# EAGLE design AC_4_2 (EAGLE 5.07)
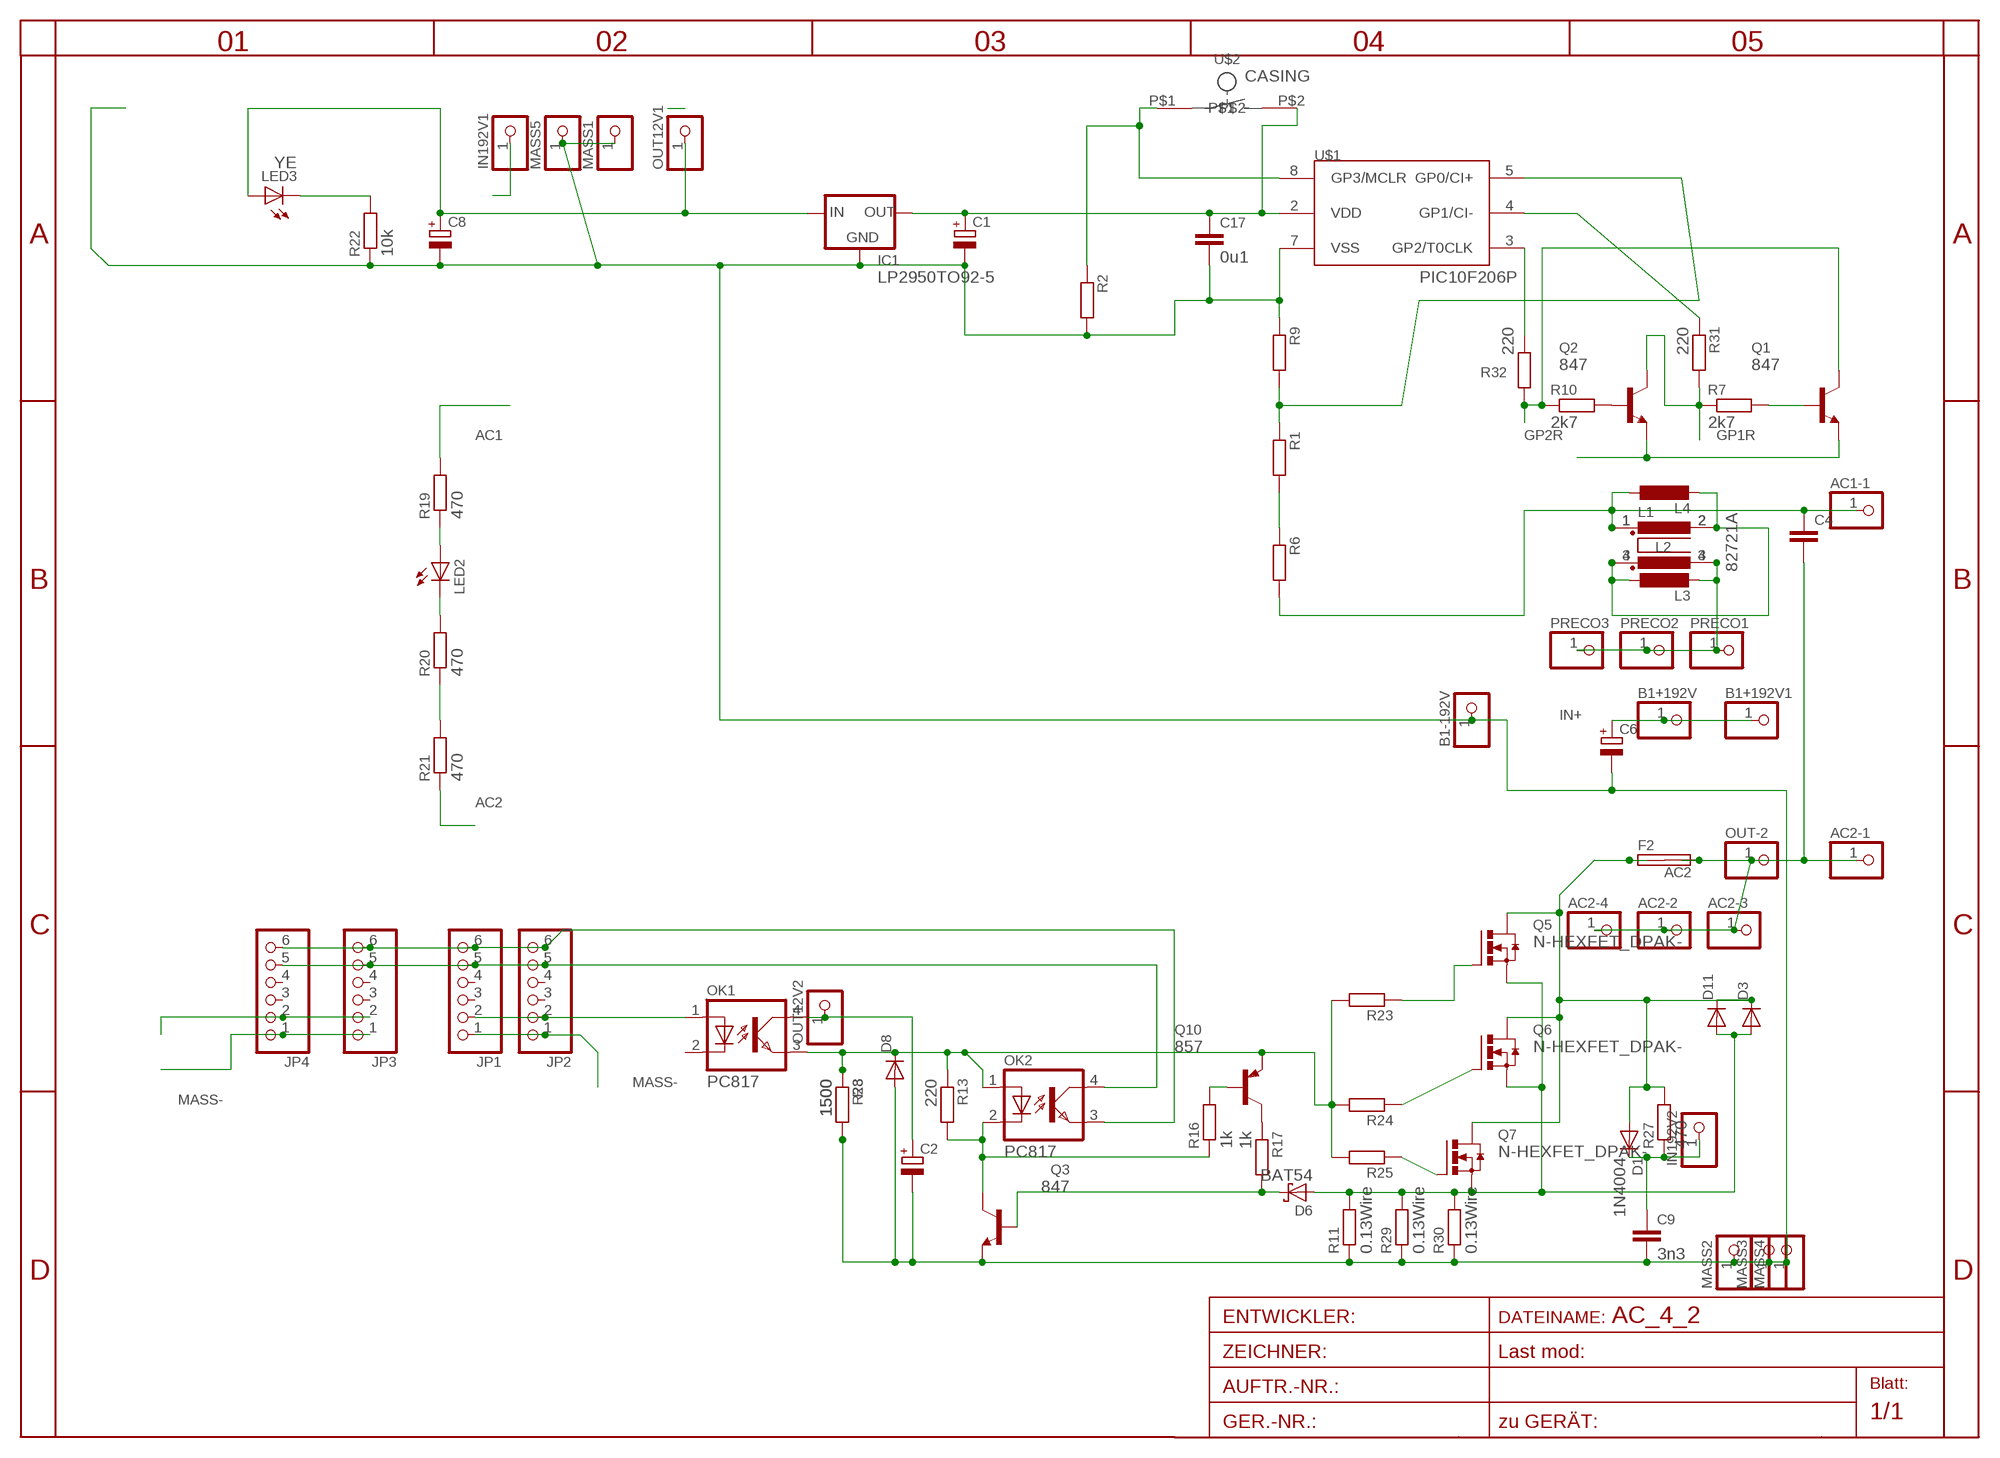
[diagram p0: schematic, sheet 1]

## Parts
AC1-1  PINHD-1X14.5MM  [1X4MM5]
AC2-1  PINHD-1X14.5MM  [1X4MM5]
AC2-2  PINHD-1X12MM3  [1X2MM3]
AC2-3  PINHD-1X12MM3  [1X2MM3]
AC2-4  PINHD-1X12MM3  [1X2MM3]
B1+192V  PINHD-1X12MM3  [1X2MM3]
B1+192V1  PINHD-1X12MM3  [1X2MM3]
B1-192V  PINHD-1X12MM3  [1X2MM3]
C1  CPOL-EUE5-6  [E5-6]
C2  CPOL-EUE2.5-5  [E2,5-5]
C4  C-EU225-108X268  [C225-108X268]
C6  CPOL-EUE10-20  [EB20D]
C8  CPOL-EUE5-5  [E5-5]
C9  3n3  C-EU102-043X133  [C102-043X133]
C17  0u1  C-EUC1206  [C1206]
D1  1N4004  [DO41-10]
D3  DIODE-SMC  [SMC]
D6  BAT54  [SOT23]
D8  DIODE-MINIMELF  [MINIMELF]
D11  DIODE-SMC  [SMC]
F2  SHK20L7MM5  [7MM5]
IC1  LP2950TO92-5  [T092-5]
IN192V1  PINHD-1X11MM6  [1X1MM8]
IN192V2  PINHD-1X11MM0  [1X1MM0]
JP1  PINHD-1X6  [1X06BOX]
JP2  PINHD-1X6  [1X06BOX]
JP3  PINHD-1X6  [1X06BOX]
JP4  PINHD-1X6  [1X06BOX]
L1  R1405VB1  [B1]
L2  82721A  [82721A]
L3  L-EU2200-15.24  [2200-15.24]
L4  L-EU2200-15.24  [2200-15.24]
LED2  LED3MM  [LED3MM]
LED3  YE  LEDCHIPLED_1206  [CHIPLED_1206]
MASS1  PINHD-1X11MM6  [1X1MM8]
MASS2  PINHD-1X11MM0  [1X1MM0]
MASS3  PINHD-1X11MM6  [1X1MM8]
MASS4  PINHD-1X11MM6  [1X1MM8]
MASS5  PINHD-1X11MM6  [1X1MM8]
OK1  PC817  [DIL04]
OK2  PC817  [DIL04]
OUT12V1  PINHD-1X11MM6  [1X1MM8]
OUT12V2  PINHD-1X11MM0  [1X1MM0]
OUT-2  PINHD-1X12MM3  [1X2MM3]
PRECO1  PINHD-1X12MM3  [1X2MM3]
PRECO2  PINHD-1X12MM3  [1X2MM3]
PRECO3  PINHD-1X12MM3  [1X2MM3]
Q1  847  BC847ALT1SMD  [SOT23]
Q2  847  BC847ALT1SMD  [SOT23]
Q3  847  BC846ALT1SMD  [SOT23]
Q5  N-HEXFET_DPAK-  [TO252]
Q6  N-HEXFET_DPAK-  [TO252]
Q7  N-HEXFET_DPAK-  [TO252]
Q10  857  BC857ALT1SMD  [SOT23-BEC]
R1  R-EU_0207/60  [0207/60]
R2  R-EU_R0805  [R0805]
R3  1500  R-EU_R0805  [R0805]
R6  R-EU_0207/10  [0207/10]
R7  2k7  R-EU_R1206  [R1206]
R9  R-EU_R0805  [R0805]
R10  2k7  R-EU_R1206  [R1206]
R11  0.13Wire  R-EU_0204/5  [0204/5]
R13  220  R-EU_R1206  [R1206]
R16  1k  R-EU_R0805  [R0805]
R17  1k  R-EU_R0805  [R0805]
R19  470  R-EU_0204/5  [0204/5]
R20  470  R-EU_0204/2V  [0204V]
R21  470  R-EU_0204/5  [0204/5]
R22  10k  R-EU_R1206  [R1206]
R23  R-EU_0207/15  [0207/15]
R24  R-EU_0207/10  [0207/10]
R25  R-EU_0207/12  [0207/12]
R27  470  R-EU_0207/10  [0207/10]
R28  1500  R-EU_R1206  [R1206]
R29  0.13Wire  R-EU_0204/5  [0204/5]
R30  0.13Wire  R-EU_0204/5  [0204/5]
R31  220  R-EU_R1206  [R1206]
R32  220  R-EU_R1206  [R1206]
U$1  PIC10F206P  [DIL8]
U$2  CASING  [CASING]

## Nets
AC1: AC1-1.1 C4.1 L1.1 L2.1 L4.1 R6.2 R19.2
AC2: AC2-1.1 AC2-2.1 AC2-3.1 AC2-4.1 C4.2 F2.2A F2.2B OUT-2.1 R21.1
BATT+: C8.+ IC1.3(IN) LED3.A OUT12V1.1
D1: D1.A D3.C D11.C F2.1A F2.1B Q5.3(D) Q6.3(D) Q7.3(D) R27.2
GP1R: JP3.2 JP4.2 Q2.3(C) R7.1 R31.2
GP2R: JP1.2 JP2.2 OK1.1(A) Q1.3(C) R10.1 R32.2
GP3: JP1.6 JP2.6 JP3.6 JP4.6 OK2.3(EMIT) R2.1 U$1.8(GP3/MCLR) U$2.P$1
IN+: B1+192V1.1 B1+192V.1 C6.+ IN192V1.1
INN: L1.2 L1.3 L2.2 L2.4 L3.1 L4.2
MASS-: B1-192V.1 C1.- C2.- C6.- C8.- C9.2 C17.2 D8.A IC1.2(GND) JP1.1 JP2.1 JP3.1 JP4.1 MASS1.1 MASS2.1 MASS3.1 MASS4.1 MASS5.1 Q1.2(E) Q2.2(E) Q3.2(E) R2.2 R3.2 R9.1 R11.1 R22.1 R28.2 R29.1 R30.1 U$1.7(VSS)
N$1: R1.1 R9.2 U$1.5(GP0/CI+)
N$2: C2.+ OK1.4(COL) OUT12V2.1
N$3: R1.2 R6.1
N$4: Q2.1(B) R10.2
N$6: LED2.A R19.1
N$7: Q1.1(B) R7.2
N$9: LED2.K(C) R20.2
N$11: D6.3(C) Q3.1(B) R17.2
N$12: OK2.2(C) Q3.3(C) R13.2 R16.1
N$13: R20.1 R21.2
N$15: LED3.C R22.2
N$16: Q10.B R16.2
N$17: Q10.C R17.1
N$20: C9.1 D1.C IN192V2.1 R27.1
N$25: Q7.1(G) R25.1
N$26: Q6.1(G) R24.1
N$27: Q5.1(G) R23.1
N$39: R31.1 U$1.4(GP1/CI-)
N$43: R32.1 U$1.3(GP2/T0CLK)
PP1: D8.C OK1.3(EMIT) OK2.1(A) Q10.E R3.1 R13.1 R23.2 R24.2 R25.2 R28.1
PRECOIL: L1.4 L2.3 L3.2 PRECO1.1 PRECO2.1 PRECO3.1
SRC1: D3.A D6.1(A) D11.A Q5.2(S) Q6.2(S) Q7.2(S) R11.2 R29.2 R30.2
VDD: C1.+ C17.1 IC1.1(OUT) JP1.5 JP2.5 JP3.5 JP4.5 OK2.4(COL) U$1.2(VDD) U$2.P$2
Unconnected: JP1.3 JP1.4 JP2.3 JP2.4 JP3.3 JP3.4 JP4.3 JP4.4 OK1.2(C)

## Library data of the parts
AC1-1 AC2-1-AC2-4 B1+192V B1+192V1 B1-192V IN192V1 IN192V2 MASS1-MASS5 OUT12V1 OUT12V2 OUT-2 PRECO1-PRECO3 = pinhead:PINHD-1X1: PIN HEADER
C1 C2 C8 = rcl-2:CPOL-EU: POLARIZED CAPACITOR, European symbol
C4 = rcl:C-EU: CAPACITOR, European symbol
C6 = rcl:CPOL-EU: POLARIZED CAPACITOR, European symbol
C9 C17 = rcl-2:C-EU: CAPACITOR, European symbol
D1 = diode:1N4004: DIODE
D3 D8 D11 = diode:DIODE-: DIODE
D6 = diode:BAT54: Schottky Diodes
F2 = fuse:SHK20L: FUSE HOLDER 5 x 20 mm, SH contact, SHH1 Schukat, E1073 Buerklin
IC1 = v-reg:LP2950?*: Source: http://cache.national.com/ds/LP/LP2950.pdf
JP1-JP4 = pinhead:PINHD-1X6: PIN HEADER
L1 = inductor-nkl:R1405V: Übertrager (verlustarm) bis typ. 400kHz Power transformer (low loss) up to typ. 400kHz
L2 = inductors:82721A: FILTER
L3 L4 = rcl:L-EU: INDUCTOR, European symbol
LED2 LED3 = led:LED: LED
OK1 OK2 = optocoupler:PC817: SHARP OPTO COUPLER
Q1 Q2 = transistor-npn:BC847*: NPN Transistor
Q3 = transistor-npn:BC846*: NPN Transistor
Q5-Q7 = transistor-power:N-HEXFET_?-*: HEXFET® Power MOSFET
Q10 = transistor-pnp:BC857*: PNP Transistror
R1-R3 R6 R7 R9-R11 R13 R16 R17 R19-R25 R27-R32 = rcl-2:R-EU_: RESISTOR, European symbol
U$1 = microchip-5:PIC10F2*: uPC nW 0,25/0,5k Program Flash memory Comparator
U$2 = button:CASING

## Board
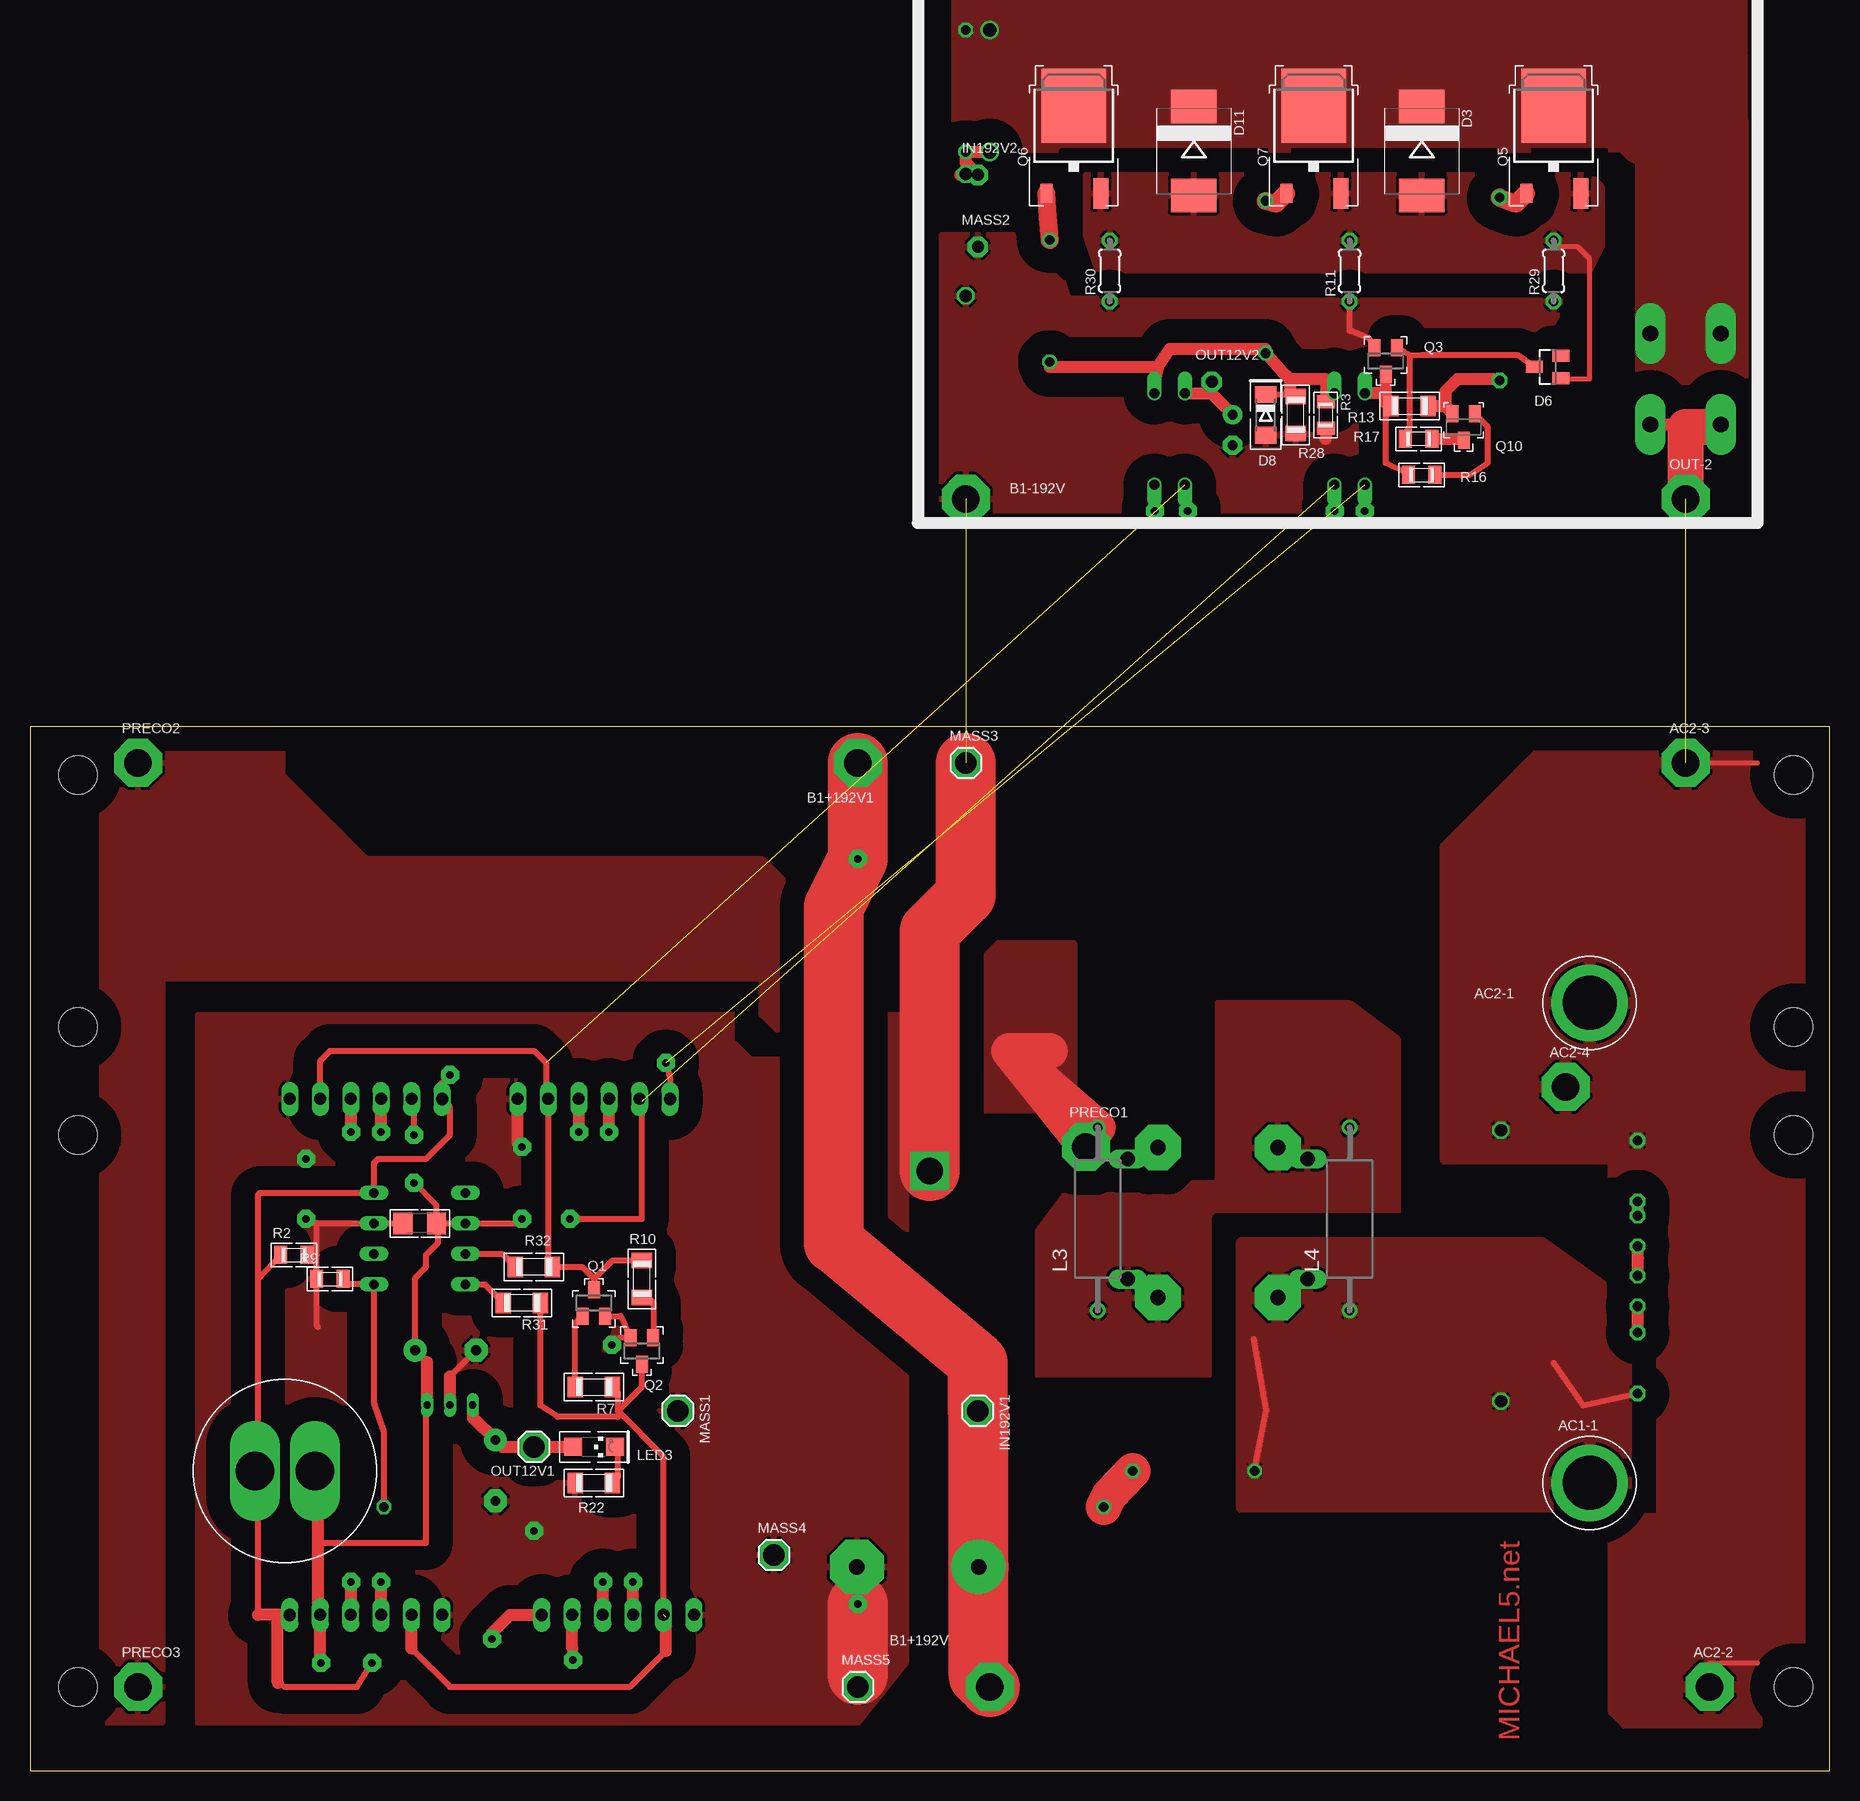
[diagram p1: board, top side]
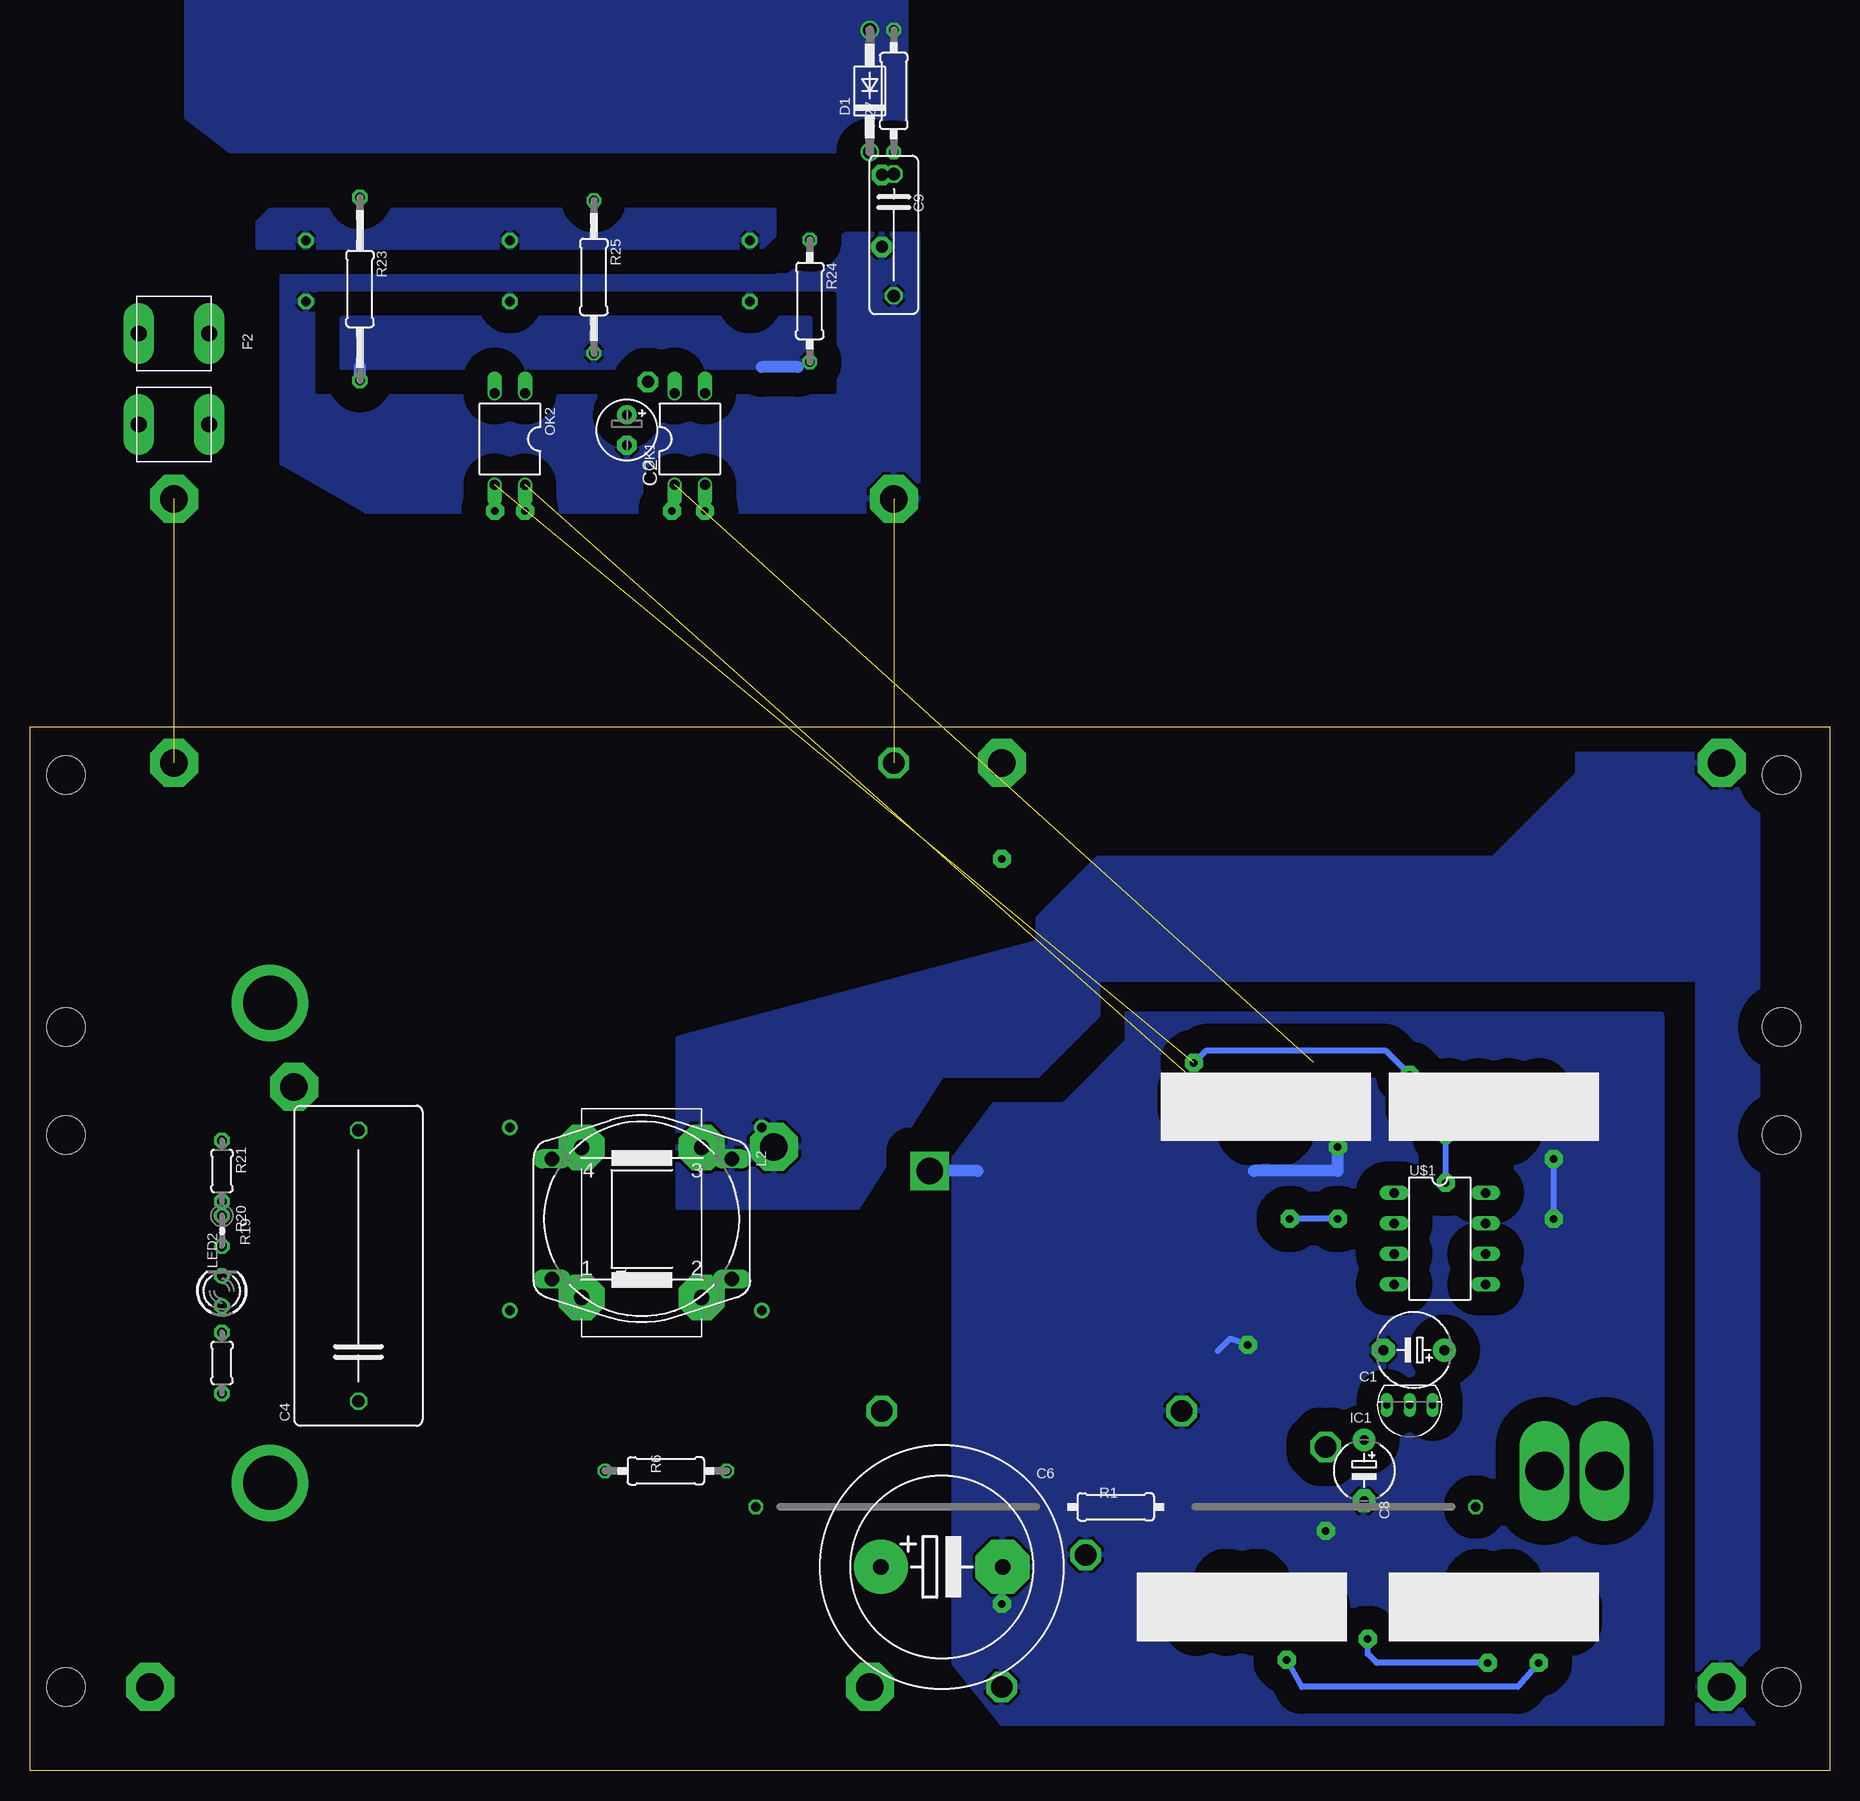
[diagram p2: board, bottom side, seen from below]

Size 150 x 87 mm. Coordinates in mm from the lower left corner, seen from the top.
Outline: 0,0 150,0 150,87 0,87 0,0
Copper layers (1*16): Top 0.035mm / dielectric 1.5mm / Bottom 0.035mm
Design rules "default *": minimum track width 12mil, minimum drill 24mil, track to track 8mil, track to pad 8mil, pad to pad 8mil, via to via 8mil, smd to smd 8mil, copper to edge 40mil, drill to drill 8mil, minimum pad ring 8mil, minimum via ring 8mil, stop-mask expansion 4mil, vias tented up to drill 0mil, thermal gap 10mil
Holes 3.2 mm at 4,83 4,7 4,62 4,53 147,83 147,7 147,62 147,53

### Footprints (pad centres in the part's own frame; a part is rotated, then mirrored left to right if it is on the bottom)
1X4MM5 = drill 4.5 pad 6.35 round: 1 0,0
1X2MM3 = drill 2.3 pad 4 octagon: 1 0,0
E5-6 = drill 0.813 pad 1.905 round: + -2.54,0 | drill 0.813 pad 1.905 octagon: - 2.54,0
E2,5-5 = drill 0.813 pad 1.6 round: + -1.27,0 | drill 0.813 pad 1.6 octagon: - 1.27,0
C225-108X268 = drill 1.016 octagon: 1 -11.303,0; 2 11.303,0
EB20D = drill 1.3 pad 4.5 round: + -5.08,0 | drill 1.3 pad 4.5 octagon: - 5.08,0
E5-5 = drill 0.813 pad 1.905 round: + -2.54,0 | drill 0.813 pad 1.905 octagon: - 2.54,0
C102-043X133 = drill 1.016 octagon: 1 -5.08,0; 2 5.08,0
C1206 = smd 1.6 x 1.8: 1 -1.4,0; 2 1.4,0
DO41-10 = drill 1.118 round: A 5.08,0; C -5.08,0
SMC = smd 2.8 x 3.8: A 3.7,0; C -3.7,0
SOT23 = smd 1 x 1.4: 1 -0.95,-1.1; 2 0.95,-1.1; 3 0,1.1
MINIMELF = smd 1.4 x 1.8: A 1.7,0; C -1.7,0
7MM5 = drill 1.3 pad 2.54 long: 1A -3.8,2.94; 1B -3.8,-2.94; 2A 3.8,2.94; 2B 3.8,-2.94
T092-5 = drill 0.6 pad 0.813 long: 1 -1.905,0; 2 0,0; 3 1.905,0
1X1MM8 = drill 1.8 pad 2.54 octagon: 1 0,0
1X1MM0 = drill 1 pad 1.676 octagon: 1 0,0
1X06BOX = drill 1 long: 1 -6.35,0; 2 -3.81,0; 3 -1.27,0; 4 1.27,0; 5 3.81,0 | drill 1.016 long: 6 6.35,0
B1 = drill 1.27 pad 3.81 octagon: 1 -6.25,5; 2 -6.25,-5; 3 6.25,5; 4 6.25,-5
82721A = drill 1.194 long: 1 7.493,5.004; 2 -7.493,5.004; 3 -7.493,-5.004; 4 7.493,-5.004
2200-15.24 = drill 0.8 pad 1.27 round: 1 -7.62,0; 2 7.62,0
LED3MM = drill 0.8 pad 1.27 octagon: A -1.27,0; K 1.27,0
CHIPLED_1206 = smd 1.5 x 1.5: A 0,-1.75; C 0,1.75
DIL04 = drill 0.813 offset: 1 -1.27,-3.81; 2 1.27,-3.81; 3 1.27,3.81; 4 -1.27,3.81
TO252 = smd 1 x 1.6: 1 -2.28,-3.53 | smd 1.27 x 2.54: 2 2.28,-3.53 | smd 5.4 x 6.2: 3 0,3.77
SOT23-BEC = smd 1 x 1.4: B -0.95,-1.1; C 0,1.1; E 0.95,-1.1
0207/60 = drill 0.813 octagon: 1 -30,0; 2 30,0
R0805 = smd 1.1 x 1.5: 1 -1.1,0; 2 1.1,0
0207/10 = drill 0.813 octagon: 1 -5.08,0; 2 5.08,0
R1206 = smd 1.3 x 1.7: 1 -1.55,0; 2 1.55,0
0204/5 = drill 0.8 pad 1.27 octagon: 1 -2.54,0; 2 2.54,0
0204V = drill 0.8 pad 1.27 octagon: 1 -1.27,0; 2 1.27,0
0207/15 = drill 0.8 pad 1.27 octagon: 1 -7.62,0; 2 7.62,0
0207/12 = drill 0.813 octagon: 1 -6.35,0; 2 6.35,0
DIL8 = drill 0.8 long: 1 -3.81,-3.81; 2 -1.27,-3.81; 3 1.27,-3.81; 4 3.81,-3.81; 5 3.81,3.81; 6 1.27,3.81; 7 -1.27,3.81; 8 -3.81,3.81
CASING = drill 3.2 pad 3.81 long: P$1 -2.5,0; P$2 2.5,0

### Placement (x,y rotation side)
AC1-1  130,24 0 top
AC2-1  130,64 0 top
AC2-2  140,7 0 top
AC2-3  138,84 0 top
AC2-4  128,57 0 top
B1+192V  80,7 0 top
B1+192V1  69,84 180 top
B1-192V  not placed on the board
C1  34.65,35.07 180 bottom
C2  100.25,111.75 270 bottom  (outside the outline)
C4  122.62,42.1 90 bottom
C6  74,17 0 bottom
C8  38.8,25.05 270 bottom
C9  78,128 270 bottom  (outside the outline)
C17  32.49,45.63 180 top
D1  80,140 90 bottom  (outside the outline)
D3  not placed on the board
D6  126.5,117 90 top  (outside the outline)
D8  103,113 270 top  (outside the outline)
D11  not placed on the board
F2  138,116 270 bottom  (outside the outline)
IC1  35,30.5 180 bottom
IN192V1  79,30 270 top
IN192V2  79,133 0 top  (outside the outline)
JP1  47,56 180 bottom
JP2  28,56 180 bottom
JP3  28,13 0 bottom
JP4  49,13 0 bottom
L1  99.03,45.7 90 bottom
L2  99,46 180 bottom
L3  89,46 90 top
L4  110,46 90 top
LED2  134,40 90 bottom
LED3  47,27 270 top
MASS1  54,30 270 top
MASS2  not placed on the board
MASS3  78,84 0 top
MASS4  62,18 0 top
MASS5  69,7 0 top
OK1  95,111 0 bottom  (outside the outline)
OK2  110,111 180 bottom  (outside the outline)
OUT12V1  42,27 270 top
OUT12V2  98.5,115.75 0 top  (outside the outline)
OUT-2  138,106 0 top  (outside the outline)
PRECO1  88,52 0 top
PRECO2  9,84 0 top
PRECO3  9,7 0 top
Q1  47,39 0 top
Q2  51,35 180 top
Q3  113,117.5 180 top  (outside the outline)
Q5  127,135 0 top  (outside the outline)
Q6  87,135 0 top  (outside the outline)
Q7  107,135 0 top  (outside the outline)
Q10  119.5,112 180 top  (outside the outline)
R1  59.5,22 180 bottom
R2  22,43 0 top
R3  108,113 270 top  (outside the outline)
R6  97,25 180 bottom
R7  47,32 180 top
R9  25,41 0 top
R10  51,41 270 top
R11  110,125 90 top  (outside the outline)
R13  115,113.75 180 top  (outside the outline)
R16  116,108 0 top  (outside the outline)
R17  115.75,111 180 top  (outside the outline)
R19  134,34 270 bottom
R20  134,45 270 bottom
R21  134,50 270 bottom
R22  47,24 0 top
R23  122.5,123.5 270 bottom  (outside the outline)
R24  85,122.5 270 bottom  (outside the outline)
R25  103,124.5 270 bottom  (outside the outline)
R27  78,140 90 bottom  (outside the outline)
R28  105.5,113 270 top  (outside the outline)
R29  127,125 90 top  (outside the outline)
R30  not placed on the board
R31  41,39 0 top
R32  42,42 0 top
U$1  32.49,44.36 270 bottom
U$2  21.25,25 0 top

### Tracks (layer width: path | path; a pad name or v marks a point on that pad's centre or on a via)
AC1
  Top 0.5: R6.2 103.08,30.08 102,36 | R19.2 129.46,30.46 127,34
  pour Top (isolate 2): 101,44 126,44 133,39 133,22 101,22
AC2  (1 unrouted)
  Top 0.406: AC2-3.1 144,84 | 144,9 140,9 AC2-2.1
  Top 1: F2.2A F2.2B 140.74,112 140,112
  Top 3: OUT-2.1 138,112 140,112
  pour Top (isolate 2, rank 2): 130,86 146,86 148,84 148,8 144,4 133,4 132,5 132,51 118,51 118,77 126,85
BATT+
  Top 1: IC1.3 36.91,29.48 C8.+ 39.38,27 OUT12V1.1 LED3.A
D1
  pour Top (isolate 2, rank 2, no thermals): 77,151 142.89,151 143,135 143,114 134,114 134,134 132,135 77,135
  pour Bottom (isolate 2, rank 2, no thermals): 77,151 137,151 137,137.82 133.35,135 77,135
GP1R  (1 unrouted)
  Top 0.5: R31.2 42.55,30.45 44,29.5 49,29.5 49,30 | 49,30 49,31.55 R7.1 | Q2.3 51,32 49,30 | 49,30 52.81,26.19 JP4.2 | 31.81,10.19 35,7 50,7 53,10
  Top 1: 53,10 53,12.81 | 31.81,10.19 JP3.2
GP2R  (1 unrouted)
  Top 0.5: R10.1 48.55,42.55 47,41 | 47,41 Q1.3 | 47,41 46,42 R32.2 43.19,42.36 JP1.2 43,56.19 43,59 42,60 25,60 24.19,59.19 JP2.2
GP3  (via drill 0.6 pad 1.5)  (1 unrouted)
  Top 0.5: 20.65,7.35 21.25,7 27.25,7 v28.5,9 | 19,13 19,21.5 U$2.P$1 19,26.5 19,41 | 19,41 R2.1 | 19,41 19,48 19.17,48.17 U$1.8 28.68,50.68 29,51 33,51 35,53 35,55.35 JP2.6 34,56.35 34,57 v35,58 | 20.65,12.65 21,13 | v38.5,11 38.5,11.5 | JP1.6 53.35,57.65 v53,59
  Top 1: 19,13 JP3.6 21,13 | 20.65,7.35 20.65,12.65 | 38.5,11.5 40,13 JP4.6
  Bottom 0.5: v28.5,9 37.75,9 38.5,9.75 v38.5,11 | v53,59 52,60 37,60 v35,58
IN+  (via drill 0.6 pad 1.5)
  Top 5: B1+192V.1 79.08,7.92 C6.+ 79.08,29.92 IN192V1.1 79,34 67,44 67,72 v69,76 B1+192V1.1
INN
  pour Top (isolate 2, rank 2): 99,64 110,64 114,61 114,46 99,46 99,33 84,33 84,45 87,49 99,49
MASS-  (via drill 0.6 pad 1.5, 2.2 pad 3)  (1 unrouted)
  Top 0.5: Q3.2 111.62,119.38 110,120 R11.1 | U$1.7 28.68,46 | 24,45.63 23.37,45.63 v23,46 | 24,45.63 U$1.7 | Q1.2 49.25,37.9 Q2.2 49.1,36.1 v48.5,35.5 | 23.9,43 R9.1 23.9,37.1 24,37 | 23.9,43 23.9,45.53 24,45.63 | 35,32.88 C1.- | U$1.7 C17.2 | 23.9,43 R2.2
  Top 1: IC1.2 35,32.88 | JP1.1 40.65,52.35 v41,52 | R3.2 108,111
  Top 5: 69,8 v69,13.92 | MASS3.1 78,73 75,70 v75,50
  Bottom 0.5: v69,13.92 C6.- | v23,46 v23,51 | v48.5,35.5 50,36 51,35
  Bottom 1: v41,52 41,50 48,50 | 71,50 v75,50
  other vias: 42,20
  pour Top (isolate 2, rank 3): 76,128 82,128 86,124 129,124 119,108 117,105 76,105
  pour Bottom (isolate 2, rank 3): 76,128 82,128 86,125 129,125 129,109 122,105 76,105
  pour Bottom (isolate 2, rank 3): 14,63 64,63 73,51 73,9 69,4 14,4
  pour Top (isolate 2, rank 3): 14,63 73,63 73,9 69,4 14,4
N$1
  Top 0.5: R1.1 29.5,28.25 28.68,30.68 U$1.5 26.55,40.55 R9.2
N$2
  Top 0.5: 98.46,114.81 98.5,114.77 98.64,114.64
  Top 1: OK1.4 98.46,114.81 | 98.64,114.64 C2.+ | 98.5,114.77 OUT12V2.1
N$3
  Top 3: R6.1 90,23 R1.2
N$4
  Top 0.5: R10.2 51.55,39.45 52,39 52,36.15 Q2.1
N$5  (via drill 0.6 pad 1.5)
  Top 1: 50.25,13 v50.25,15.75
N$6
  Top 1.016: R19.1 LED2.A
N$7
  Top 0.5: R7.2 45.45,37.3 Q1.1
N$8  (via drill 0.6 pad 1.5)
  other vias: 47.75,15.75
N$9
  Top 1.016: R20.2 134.04,42.73 LED2.K
N$10  (via drill 0.6 pad 1.5)
  other vias: 26.75,15.75
N$11
  Top 0.5: R17.2 114.9,111.9 115,112 115,117.96 | 115,117.96 Q3.1 | 115,117.96 116,118 124,118 D6.3
N$12
  Top 0.5: R16.1 114.9,108.1 113,109 113,114
  Top 1: 113,114.81 113,114 R13.2 | 113,114.81 OK2.2 | 113,114.81 Q3.3
N$13
  Top 1.016: R20.1 R21.2
N$15
  Top 0.5: LED3.C 49,27 49,24.45 R22.2
N$16
  Top 0.5: R16.2 120,108 121.5,109 121.5,112 Q10.B
N$17
  Top 1: R17.1 119.35,111 Q10.C
N$18  (via drill 0.6 pad 1.5)
  Top 1: 29.25,13 v29.25,15.75
N$19  (via drill 0.6 pad 1.5)
  Top 1: v48.25,53.25 48.25,56
N$20
  Top 1: D1.C R27.1 78,134 IN192V2.1 77.54,133 C9.1
N$21  (via drill 0.6 pad 1.5)
  other vias: 111.25,105
N$22  (via drill 0.6 pad 1.5)
  other vias: 108.75,105
N$23  (via drill 0.6 pad 1.5)
  other vias: 96.5,105
N$24  (via drill 0.6 pad 1.5)
  other vias: 93.75,105
N$25
  Top 1.5: R25.1 103.87,130.62 Q7.1
N$26
  Top 1.5: Q6.1 84.85,129.47 R24.1
N$27
  Top 1.5: R23.1 123.87,130.62 Q5.1
N$28  (via drill 0.6 pad 1.5)
  Top 1: v45.75,53.25 45.75,56
N$29  (via drill 0.6 pad 1.5)
  Top 1: v29.25,53.25 29.25,56
N$30  (via drill 0.6 pad 1.5)
  Top 1: v26.75,53.25 26.75,56
N$31
  Top 1: 47.75,13 47.75,15.5
N$32
  Top 1: 26.75,13 26.75,15.5
N$39
  Top 0.5: U$1.4 37.9,40.55 R31.1
N$43
  Top 0.5: U$1.3 39.36,43.09 R32.1
PP1
  Top 0.406: 103,118.5 R25.2
  Top 0.5: 105.85,114.7 105,114.7 D8.C | 122,116 R23.2 | R28.1 105.45,114.55 105,115
  Top 1: 103,118.5 95,118.5 94,117 | 94,117 93.75,116.08 OK1.3 | R25.2 104.35,116.65 105,116 | 105,116 105,115 105,114.7 | 108,116 OK2.1 | 105,116 108,116 | R13.1 118,113.75 | 118,113.75 Q10.E | 122,116 119,116 118,115 118,113.75 | 85,117 94,117 | 108,116 R3.1
  Bottom 0.406: R25.2 103,119
  Bottom 1: R23.2 122.5,117 | 86,117 89,117
  pour Bottom (isolate 2, rank 2): 85,121 124,121 124,117 85,117
PRECOIL
  Top 3: PRECO1.1 81.62,60 | 81.62,60 85,60 | 81.62,60 L3.2
  pour Bottom (isolate 2): 6,86 21,86 21,83 28,76 61,76 66,71 66,69 96,61 96,47 81,47 74,58 66,58 61,63 61,66 11,66 11,4 6,4
  pour Top (isolate 2): 6,86 21,86 21,83 28,76 61,76 66,71 66,69 87,69 87,55 77,55 74,58 66,58 61,63 61,66 11,66 11,4 6,4
SRC1
  Top 0.406: R29.2 127.54,127 129,127 130,126 130,116 127.65,116 D6.1
  pour Top (isolate 2): 88,133 130,133 131,132 131,127 130,125 89,125 88,128
  pour Bottom (isolate 2): 88,130 130,130 131,129 131,127 89,127 88,128
VDD  (via drill 0.6 pad 1.5)  (1 unrouted)
  Top 0.5: 33.09,34.09 C1.+ 32.11,41.11 33,42 33,43 34,44 34,45.52 C17.1 | C17.1 U$1.2 | 24,19 33,19 33,30 33.09,30.09 IC1.1 | v45.25,9.25 45.19,10.19 | 24,22.75 U$2.P$2 | C17.1 40.63,45.63 v41,46 | v45,46 51,46 51,55.81 JP1.5 | C17.1 33.89,47.11 v32,49 | v32,53 32,55.81 JP2.5 | JP3.5 24,13.19 | v24.25,9 24.19,9.31
  Top 1: IC1.1 33.09,34.09 | 24,22.75 24,19 24,13.19 | 45.19,10.19 JP4.5 | 24.19,9.31 JP3.5
  Bottom 0.5: v45.25,9.25 44,7 26,7 v24.25,9 | v41,46 v45,46 | v32,49 v32,53

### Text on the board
Top: MICHAEL5.net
